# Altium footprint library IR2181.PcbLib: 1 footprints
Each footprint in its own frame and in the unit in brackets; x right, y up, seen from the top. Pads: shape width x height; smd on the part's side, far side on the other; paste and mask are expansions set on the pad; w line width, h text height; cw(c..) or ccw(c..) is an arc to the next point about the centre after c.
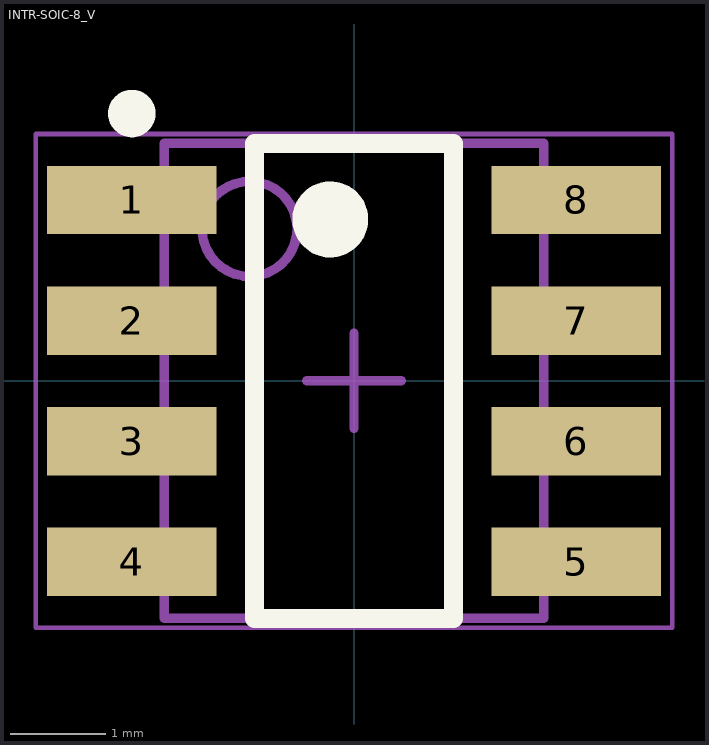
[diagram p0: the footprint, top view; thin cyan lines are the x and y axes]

## INTR-SOIC-8_V [mm]
height 1.75
pads (8):
  rect 1.78x0.72 smd: 1(-2.34,1.905) 2(-2.34,0.635) 3(-2.34,-0.635) 4(-2.34,-1.905) 5(2.34,-1.905) 6(2.34,-0.635) 7(2.34,0.635) 8(2.34,1.905)
Top Overlay:
  circle w0.25: c-2.34,2.815 r0.125
  circle w0.4: c-0.25,1.7 r0.2
  lines w0.2: -1.05,-2.5 -1.05,2.5 1.05,2.5 1.05,-2.5 -1.05,-2.5
Mechanical 13:
  circle w0.1: c-1.1,1.6 r0.5
  lines w0.1: -2,-2.5 -2,2.5 2,2.5 2,-2.5 -2,-2.5
Mechanical 15:
  lines w0.05: -3.35,-2.6 -3.35,2.6 3.35,2.6 3.35,-2.6 -3.35,-2.6
  lines w0.1: -0.5,0 0.5,0 ; 0,-0.5 0,0.5
3D body "SOIC127P600X175-8L.step": height 1.75, standoff 0, extent -3,-2.5 3,2.5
